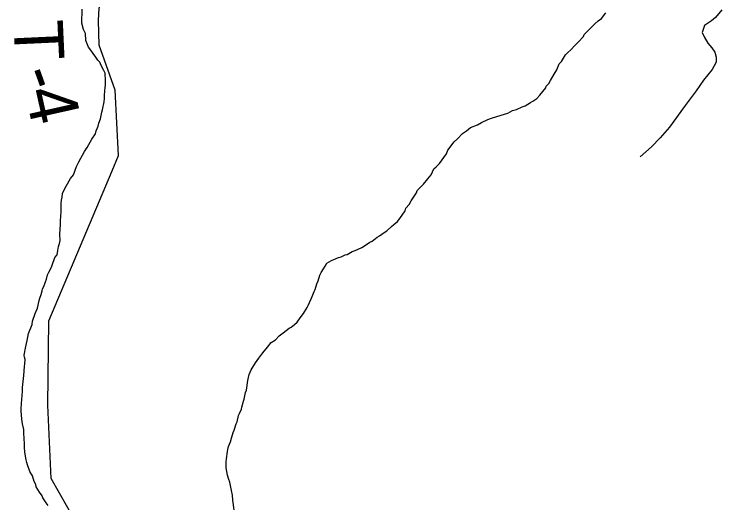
# Model space of a CAD drawing. Extents: x 1310247 to 1664935, y 235267 to 584339.
# Drawn here: x 1514062 to 1518358, y 293661 to 296629 of the extents above; entities that cross this region are included whole.
import ezdxf

# ---------------------------------------------------------------- set-up
doc = ezdxf.new("R2010")
doc.units = 0
for name, color, linetype in [('GM_X_Minor_River', 7, 'Continuous'), ('GM_X_Township_Road', 7, 'Continuous'), ('GM_X_Township_Road_Text', 7, 'Continuous'), ('GM_X_Township_ROW', 7, 'Continuous')]:
    doc.layers.add(name, color=color, linetype=linetype)

msp = doc.modelspace()

# ---------------------------------------------------------------- linework, layer by layer
at = {"layer": 'GM_X_Minor_River'}
for points in [[(1514421.7, 295652.6), (1514440.4, 295704.6), (1514454.8, 295732.5), (1514489.7, 295794.3), (1514506, 295818.1), (1514532.8, 295870), (1514555.2, 295901.8), (1514559.5, 295919.8), (1514571.9, 295947.8), (1514576.1, 295965.8), (1514586.5, 295993.8), (1514595, 296033.8), (1514599.2, 296047.8), (1514607.8, 296095.9), (1514610, 296115.9), (1514610.2, 296132), (1514612.6, 296166.1), (1514614.8, 296182.1), (1514617, 296200.1), (1514617.4, 296226.2), (1514615.5, 296238.3), (1514613.7, 296258.4), (1514613.9, 296270.4), (1514606, 296286.6), (1514590.3, 296316.9), (1514582.5, 296337), (1514570.6, 296349.2), (1514556.8, 296367.5), (1514541, 296389.7), (1514527.2, 296410), (1514513.3, 296428.2), (1514497.8, 296468.6), (1514494.2, 296510.8), (1514482.5, 296535), (1514472.9, 296573.2), (1514473.9, 296659.5)], [(1515648.9, 294651.5), (1515671.3, 294675.3), (1515695.6, 294693.1), (1515732.1, 294720.7), (1515744.2, 294728.6), (1515764.5, 294744.4), (1515780.7, 294758.3), (1515797.1, 294784.1), (1515817.5, 294810), (1515840, 294847.9), (1515846.2, 294859.8), (1515864.7, 294899.7), (1515870.9, 294913.7), (1515883.3, 294943.7), (1515889.5, 294955.6), (1515900, 294991.6), (1515908.2, 295009.6), (1515916.6, 295043.6), (1515924.9, 295059.6), (1515939.2, 295081.5), (1515949.4, 295097.4), (1515959.7, 295117.4), (1515988, 295133.1), (1516030.4, 295150.6), (1516046.5, 295154.4), (1516070.7, 295166.1), (1516082.8, 295170), (1516113.2, 295187.7), (1516131.3, 295193.5), (1516171.7, 295211), (1516187.9, 295220.9), (1516220.3, 295244.6), (1516234.4, 295250.4), (1516264.8, 295274.1), (1516279, 295282), (1516307.3, 295303.7), (1516323.5, 295313.5), (1516351.9, 295339.2), (1516366.1, 295351.1), (1516388.5, 295368.9), (1516402.7, 295386.8), (1516435.4, 295434.5), (1516439.6, 295450.5), (1516460, 295472.4), (1516472.3, 295494.3), (1516505, 295544.1), (1516509.2, 295558.1), (1516529.5, 295577.9), (1516545.8, 295595.8), (1516572.3, 295629.5), (1516592.7, 295653.4), (1516609.2, 295689.3), (1516623.4, 295701.2), (1516643.7, 295721), (1516686.6, 295780.7), (1516694.9, 295802.6), (1516733.6, 295854.3), (1516753.9, 295872.1), (1516784.4, 295903.9), (1516808.7, 295919.6), (1516831.1, 295941.4), (1516875.4, 295956.9), (1516899.7, 295970.7), (1516938.1, 295988.2), (1516960.3, 295998), (1517018.7, 296015.3), (1517059, 296026.9), (1517087.4, 296044.6), (1517111.5, 296050.3), (1517145.8, 296065.9), (1517164, 296071.7), (1517196.4, 296091.4), (1517210.5, 296101.2), (1517234.8, 296117), (1517253.1, 296136.8), (1517289.8, 296180.5), (1517292, 296192.5), (1517308.2, 296208.4), (1517318.5, 296226.3), (1517339, 296264.2), (1517355.4, 296290.1), (1517369.9, 296328), (1517384.1, 296341.9), (1517408.7, 296381.7), (1517422.9, 296395.6), (1517441.2, 296411.4), (1517463.6, 296437.2), (1517488, 296461), (1517518.5, 296492.8), (1517522.6, 296504.7), (1517545, 296528.5), (1517587.7, 296570.2), (1517608, 296588), (1517628.2, 296601.8), (1517652.7, 296637.6)], [(1514269.3, 293644.9), (1514255.4, 293661.1), (1514235.7, 293691.5), (1514231.8, 293703.6), (1514216, 293725.9), (1514196.3, 293758.3), (1514194.5, 293772.3), (1514182.7, 293790.6), (1514173, 293824.8), (1514157.3, 293851.1), (1514143.7, 293891.4), (1514139.8, 293905.5), (1514134, 293921.7), (1514126.5, 293968), (1514124.9, 293998.1), (1514125.1, 294018.2), (1514119.9, 294084.5), (1514120.1, 294106.6), (1514112.5, 294140.8), (1514108.8, 294169), (1514105.4, 294219.2), (1514103.6, 294231.3), (1514105.9, 294263.4), (1514112.9, 294337.6), (1514113.1, 294361.6), (1514117.8, 294415.8), (1514120, 294433.8), (1514124.7, 294488), (1514126.9, 294506), (1514129.2, 294532.1), (1514125.4, 294546.2), (1514123.5, 294558.3), (1514132.2, 294610.4), (1514140.6, 294646.4), (1514144.9, 294666.4), (1514149.2, 294688.4), (1514171.9, 294744.4), (1514174.2, 294764.4), (1514188.8, 294810.4), (1514195, 294824.4), (1514203.2, 294842.3), (1514213.8, 294890.4), (1514218, 294904.4), (1514226.3, 294926.4), (1514232.6, 294948.4), (1514234.7, 294960.4), (1514242.9, 294974.3), (1514251.3, 295002.3), (1514257.5, 295020.3), (1514263.9, 295046.3), (1514272.1, 295062.3), (1514288.5, 295092.2), (1514292.7, 295104.2), (1514309.3, 295150.2), (1514323.6, 295168), (1514327.9, 295194.1), (1514330.2, 295218.2), (1514336.4, 295236.1), (1514340.7, 295254.2), (1514340.8, 295266.2), (1514338.9, 295278.3), (1514339.1, 295292.3), (1514343.8, 295350.5), (1514344.1, 295374.6), (1514346.8, 295430.7), (1514347.4, 295480.9), (1514349.6, 295499), (1514353.8, 295517), (1514356.1, 295539), (1514366.4, 295561), (1514376.7, 295584.9), (1514403.4, 295630.8), (1514421.7, 295652.6)], [(1515397.6, 293616.7), (1515392.1, 293662.9), (1515390.3, 293677), (1515386.6, 293707.2), (1515380.9, 293735.3), (1515371.5, 293785.7), (1515365.7, 293801.8), (1515357.9, 293828), (1515352.2, 293850.2), (1515348.5, 293874.3), (1515348.9, 293908.4), (1515351.1, 293928.5), (1515357.6, 293972.6), (1515359.8, 293984.6), (1515364, 294002.6), (1515374.4, 294030.6), (1515380.7, 294052.6), (1515391.2, 294088.6), (1515397.3, 294102.6), (1515409.8, 294140.6), (1515416, 294152.5), (1515424.5, 294190.6), (1515430.7, 294202.5), (1515441, 294230.5), (1515443.2, 294242.5), (1515453.7, 294278.5), (1515457.8, 294290.5), (1515466.3, 294330.6), (1515472.5, 294344.6), (1515481.3, 294404.7), (1515487.7, 294440.7), (1515500.1, 294468.7), (1515526.7, 294510.5), (1515547.2, 294540.4), (1515571.6, 294572.2), (1515600.1, 294606), (1515622.6, 294633.8), (1515648.9, 294651.5)]]:
    msp.add_lwpolyline(points, dxfattribs=at)
at = {"layer": 'GM_X_Township_Road'}
for points in [[(1514656.1, 295676.3), (1514695.9, 295770.7), (1514674.1, 296167.3), (1514577, 296439.6), (1514573.8, 296590), (1514577.3, 296666.1), (1514619.6, 296783.6), (1514699.9, 297002.6), (1514815.4, 297178.8), (1514959.2, 297358.6), (1515059.2, 297457), (1515124.3, 297505.9), (1515262, 297581.5), (1515356.8, 297613.8), (1515464.2, 297672), (1515553.9, 297748.5), (1515675.8, 297840.5), (1515722.7, 297879.7), (1515772.5, 297932.7), (1515834.6, 297962.5), (1515847.4, 297957.1)], [(1518357.8, 296655.1), (1518318.7, 296609.4), (1518294.3, 296587.8), (1518251.7, 296560.6), (1518238.8, 296518.3), (1518249.6, 296490.9), (1518272.5, 296452.8), (1518297.3, 296423.5), (1518314.5, 296397.4), (1518324, 296367.6), (1518324, 296337.7), (1518299.9, 296291.9), (1518246.4, 296227.6), (1518201.9, 296163.4), (1518135.7, 296075), (1518039.7, 295943.3), (1517983.1, 295878.4), (1517930.3, 295823.7), (1517862.2, 295763.3)]]:
    msp.add_lwpolyline(points, dxfattribs=at)
at = {"layer": 'GM_X_Township_ROW'}
msp.add_lwpolyline([(1514836.4, 292727.3), (1514859.5, 292795.5), (1514717.9, 293143.3), (1514438.5, 293542.3), (1514285.6, 293808.3), (1514265.6, 294253.9), (1514272.3, 294766), (1514656.1, 295676.3)], dxfattribs=at)

# ---------------------------------------------------------------- texts
at = {"layer": 'GM_X_Township_Road_Text'}
for s, rotation, p in [('T', 272.6495, (1514057.1, 296586)), ('-', 289.6968, (1514086.3, 296266.7)), ('4', 282.6544, (1514125.1, 296160))]:
    msp.add_text(s, height=300, rotation=rotation, dxfattribs=at).set_placement(p)

doc.saveas('drawing.dxf')
